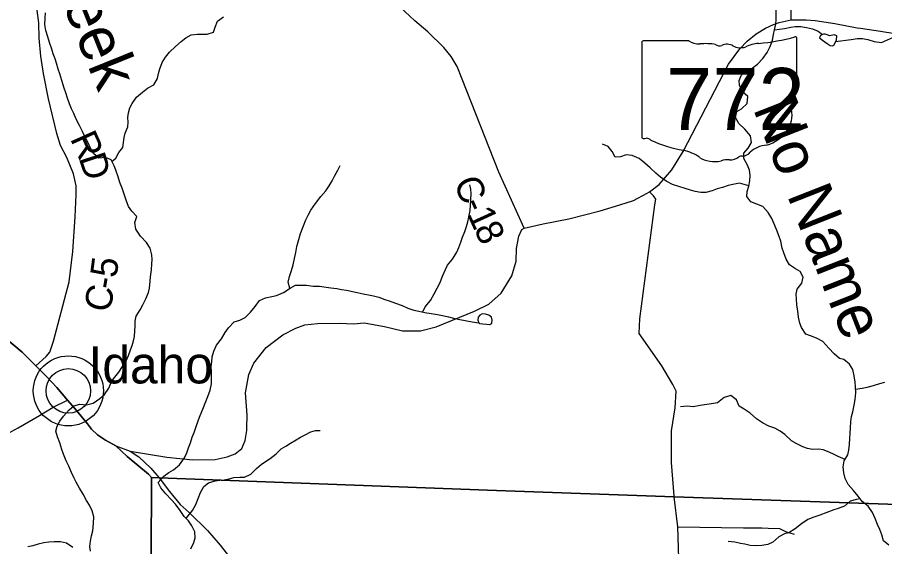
# Model space of a CAD drawing. Extents: x 1578669 to 1989827, y 208020 to 553079.
# Drawn here: x 1785723 to 1795443, y 395188 to 401117 of the extents above; entities that cross this region are included whole.
import ezdxf

# ---------------------------------------------------------------- set-up
doc = ezdxf.new("R2010")
doc.units = 0
for name, color, linetype in [('GM_X_County_Road', 7, 'Continuous'), ('GM_X_County_Road_Text', 7, 'Continuous'), ('GM_X_Minor_Lake', 7, 'Continuous'), ('GM_X_Minor_River', 7, 'Continuous'), ('GM_X_Minor_River_Text', 7, 'Continuous'), ('GM_X_State_Location', 7, 'Continuous'), ('GM_X_State_Route', 7, 'Continuous'), ('GM_X_State_Shield', 7, 'Continuous'), ('GM_X_Township', 7, 'Continuous'), ('GM_X_Township_ROW', 7, 'Continuous'), ('GM_X_Unincorporated', 7, 'Continuous'), ('GM_X_Unincorporated_Location', 7, 'Continuous'), ('GM_X_Unincorporated_Text', 7, 'Continuous')]:
    doc.layers.add(name, color=color, linetype=linetype)

msp = doc.modelspace()

# ---------------------------------------------------------------- linework, layer by layer
at = {"layer": 'GM_X_County_Road'}
for points in [[(1785929.2, 397215.1), (1786046.4, 397318.1), (1786087, 397365.8), (1786128.3, 397491.7), (1786303.3, 398154), (1786342.9, 398494.7), (1786368.9, 398883.7), (1786381.4, 399130.3), (1786382.5, 399230.7), (1786353.8, 399365.4), (1786277.6, 399546.9), (1786206.8, 399680.1), (1786166.2, 399815), (1786072.1, 400205.3), (1786016.9, 400486.9), (1785986.8, 400681.8), (1785968.9, 400884.7), (1785964.7, 401057.3), (1785914.3, 401419.1)], [(1791400.8, 398756), (1791117.4, 399381.9), (1790706, 400424.8), (1790651.4, 400567.9), (1790584.4, 400679), (1790501.4, 400780.2), (1790322.9, 400954.8), (1790178, 401078.8), (1790007.4, 401235.2)], [(1793083.8, 395759.2), (1793054.8, 396130), (1793054.8, 396484.9), (1793093.5, 396741.4), (1793107.5, 396931.1), (1793068.9, 397004.9), (1792945.9, 397212.2), (1792690.3, 397574.3), (1792698.4, 397740.9), (1792867.9, 399015.7), (1792878, 399081.9), (1792851, 399116.1), (1792808.6, 399163.9)], [(1784506.5, 395441.5), (1784631.5, 395570.1), (1784886.6, 395844.1), (1785008.2, 395985.2), (1785137.5, 396100.1), (1785270.7, 396208.9), (1785440.2, 396331.4), (1785567.3, 396428.3), (1785730.4, 396520.7), (1785972, 396658.4), (1786125, 396748.9), (1786286.1, 396828.5)], [(1796261.2, 387201.1), (1795707.2, 387735.4), (1794910.2, 388432.6), (1794803.8, 388549.1), (1794711.5, 388655.5), (1794639.2, 388792.1), (1794623.2, 388966.7), (1794641.5, 389219.6), (1794699.9, 389520.5), (1794722.3, 389934), (1794704.2, 390016.3), (1794648.1, 390174.9), (1794409.3, 390648.8), (1794305.1, 390925.9), (1794262.9, 391056.4), (1794186.7, 391188.9), (1793678.8, 391639), (1793415.8, 391864.1), (1793391.8, 391930.4), (1793156.3, 394466), (1793123.9, 395409.4), (1793084.6, 395748), (1793083.8, 395759.2)]]:
    msp.add_lwpolyline(points, dxfattribs=at)
at = {"layer": 'GM_X_Minor_Lake'}
for points in [[(1794901.3, 400863.1), (1794905.1, 400909.2), (1794875, 400921.1), (1794827, 400908.8), (1794796.9, 400920.7), (1794776.8, 400928.6), (1794756.8, 400928.5), (1794736.8, 400922.4), (1794724.8, 400914.3), (1794710.9, 400888.2), (1794747.1, 400862.3), (1794773.2, 400844.4), (1794797.3, 400824.5), (1794831.5, 400802.6), (1794857.5, 400798.8), (1794871.5, 400804.8)], [(1794871.5, 400804.8), (1794901.3, 400863.1)], [(1790903.8, 397686.3), (1791019.7, 397678), (1791039.7, 397691.9), (1791045.8, 397724), (1791038, 397758.1), (1791008.1, 397782.2), (1790970.1, 397792.4), (1790932.2, 397794.5), (1790904.1, 397780.5), (1790886.1, 397760.6), (1790882, 397724.5)], [(1790882, 397724.5), (1790894.9, 397694.3), (1790903.8, 397686.3)]]:
    msp.add_lwpolyline(points, dxfattribs=at)
at = {"layer": 'GM_X_Minor_River'}
for points in [[(1786123.6, 400706.5), (1786107.8, 400760.7), (1786082.1, 400834.9), (1786064.3, 400899.1), (1786040.5, 400969.4), (1786030.8, 401037.5), (1786035, 401107.7), (1786039.2, 401165.8)], [(1794478.7, 397760.1), (1794468.4, 397824.2), (1794460.1, 397898.3), (1794453.8, 397964.4), (1794451.5, 398014.5), (1794461.3, 398070.7), (1794515, 398141.1), (1794528.8, 398205.3), (1794494.4, 398269.3), (1794444.2, 398299.1), (1794377.9, 398344.9), (1794339.6, 398406.8), (1794311.2, 398478.8), (1794295, 398530.9), (1794278.6, 398608.9), (1794260.3, 398663), (1794232, 398741), (1794199.6, 398813), (1794177.3, 398865), (1794137, 398930.9), (1794078.6, 398996.8), (1794010.4, 399024.5), (1793944.2, 399050.2), (1793899.8, 399112.1), (1793901.6, 399166.2), (1793919.3, 399226.5), (1793931.1, 399286.6), (1793934.8, 399348.8), (1793926.5, 399406.9), (1793906.3, 399462.9), (1793865.9, 399534.8), (1793863.6, 399595), (1793911.4, 399651.3), (1793951.2, 399715.7), (1793940.8, 399789.8), (1793874.4, 399863.6), (1793808, 399929.4), (1793769.7, 399993.4), (1793785.4, 400063.6), (1793839.3, 400093.9), (1793901.2, 400150.4), (1793908.8, 400228.6), (1793848.5, 400284.4), (1793816.1, 400356.4), (1793813.9, 400408.5), (1793833.6, 400464.7), (1793897.5, 400525.2), (1793957.4, 400547.6), (1794019.3, 400592), (1794079.1, 400654.4), (1794124.9, 400724.8), (1794160.6, 400791.1), (1794184.3, 400861.4), (1794198.1, 400923.6), (1794207.8, 400975.8), (1794221.6, 401040), (1794227.3, 401092.1), (1794226.8, 401206.4)], [(1786783.1, 399500.9), (1786827.2, 399539.7), (1786859.3, 399601.7), (1786903.5, 399659.7), (1786911.7, 399715.8), (1786919.9, 399769.9), (1786930, 399820), (1786962.2, 399890), (1786964.4, 399944.1), (1786962.6, 399994.2), (1786968.7, 400046.3), (1786984.9, 400102.4), (1787009.1, 400152.4), (1787059.3, 400224.4), (1787125.4, 400280.3), (1787181.5, 400324.2), (1787253.6, 400362.1), (1787293.8, 400432.1), (1787306, 400488.2), (1787318.1, 400540.3), (1787346.3, 400610.3), (1787382.5, 400672.3), (1787428.7, 400726.3), (1787494.8, 400790.2), (1787557, 400848.1), (1787609.1, 400886.1), (1787669.1, 400919.9), (1787741.1, 400929.7), (1787797.1, 400927.5), (1787849, 400929.4), (1787921, 400951.2), (1787939.2, 401007.2), (1787967.4, 401075.3), (1788031.5, 401123.2)], [(1794208.4, 400978.2), (1794321.9, 400992.4), (1794389.9, 401008.8), (1794440, 401013.1), (1794504.1, 401013.4), (1794568.2, 401001.7), (1794632.4, 400988), (1794698.6, 400960.3), (1794746.6, 400925.4)], [(1794893.2, 400847.2), (1795065.5, 400870), (1795135.5, 400880.4), (1795193.6, 400878.7), (1795255.7, 400867), (1795325.9, 400845.3), (1795406.1, 400835.7), (1795542, 400896.5)], [(1786540.7, 395139.2), (1786536.9, 395191.3), (1786541, 395249.4), (1786555.2, 395309.5), (1786567.4, 395365.6), (1786577.7, 395449.7), (1786579.9, 395521.8), (1786560.2, 395590), (1786530.4, 395652.3), (1786496.6, 395704.5), (1786458.9, 395774.8), (1786419.1, 395845), (1786383.4, 395911.3), (1786355.6, 395961.5), (1786327.8, 396017.7), (1786300, 396088), (1786270.3, 396148.2), (1786238.5, 396222.5), (1786222.7, 396276.6), (1786197, 396352.9), (1786171.2, 396417.1), (1786155.5, 396481.3), (1786169.6, 396539.3), (1786197.8, 396595.4), (1786240, 396651.4), (1786302.1, 396721.3), (1786356.3, 396767.2), (1786422.3, 396783), (1786498.2, 396776.8), (1786574.2, 396796.6), (1786646.3, 396846.5), (1786698.4, 396894.4), (1786746.6, 396964.4), (1786770.8, 397018.4), (1786800.9, 397068.4), (1786861.1, 397144.4), (1786901.3, 397204.4), (1786939.5, 397262.4), (1786969.7, 397328.4), (1786989.9, 397392.5), (1787010, 397442.5), (1787026.2, 397492.6), (1787036.3, 397542.7), (1787040.5, 397604.8), (1787042.7, 397660.9), (1787044.9, 397715), (1787053.1, 397771.1), (1787097.3, 397841.1), (1787127.4, 397897.1), (1787163.6, 397965.2), (1787191.8, 398033.2), (1787204, 398085.3), (1787212.3, 398161.4), (1787216.4, 398211.5), (1787224.7, 398289.7), (1787230.9, 398355.8), (1787233, 398405.9), (1787231.2, 398456), (1787209.5, 398530.2), (1787171.7, 398594.5), (1787104, 398664.9), (1787050.3, 398743.2), (1787040.6, 398817.4), (1787062.8, 398885.5), (1787005, 398947.8), (1786969.2, 398998), (1786943.5, 399070.3), (1786923.7, 399126.5), (1786898, 399204.7), (1786872.2, 399267), (1786852.4, 399329.1), (1786824.7, 399405.4), (1786806.9, 399455.6), (1786773.1, 399519.8), (1786709.3, 399548.1), (1786637.3, 399538.3), (1786575.5, 399592.6), (1786547.7, 399644.8), (1786512, 399717.1), (1786484.2, 399775.3), (1786452.5, 399839.6), (1786418.7, 399905.8), (1786381, 399978.1), (1786355.2, 400038.3), (1786331.4, 400092.5), (1786307.6, 400148.7), (1786283.8, 400210.9), (1786266, 400271.1), (1786248.2, 400323.3), (1786220.5, 400409.6), (1786198.8, 400483.8), (1786181, 400538), (1786163.2, 400602.2), (1786145.4, 400652.3), (1786123.6, 400706.5)], [(1793920.2, 399231.1), (1793815.1, 399258), (1793741, 399245.6), (1793689, 399233.3), (1793625, 399210.9), (1793567, 399194.6), (1793511, 399174.2), (1793437, 399153.8), (1793380.9, 399155.5), (1793320.8, 399167.2), (1793266.7, 399183), (1793208.5, 399198.7), (1793134.3, 399222.4), (1793066.1, 399246.1), (1792995.8, 399283.8), (1792929.6, 399327.6), (1792879.3, 399371.4), (1792812.9, 399431.2), (1792756.6, 399485), (1792690.3, 399534.8), (1792612, 399568.5), (1792545.9, 399576.1), (1792481.9, 399555.8), (1792421.9, 399551.4), (1792389.5, 399613.4), (1792343.2, 399669.3), (1792279, 399695)], [(1788777.9, 398082.2), (1788759, 398152.4), (1788773.2, 398214.5), (1788793.4, 398282.5), (1788813.6, 398346.6), (1788829.9, 398414.7), (1788842.1, 398484.8), (1788856.3, 398548.9), (1788876.5, 398627), (1788894.7, 398697.1), (1788929, 398781.2), (1788957.2, 398847.2), (1788981.4, 398901.3), (1789011.5, 398957.3), (1789063.7, 399033.3), (1789123.9, 399109.2), (1789178.1, 399175.2), (1789218.3, 399231.2), (1789252.4, 399285.2), (1789278.6, 399339.2), (1789314.8, 399405.3), (1789338.9, 399457.3)], [(1790266.6, 397816.8), (1790294.9, 397874.7), (1790351.1, 397944.7), (1790393.3, 398018.7), (1790427.5, 398082.8), (1790459.7, 398148.8), (1790487.9, 398218.8), (1790520.1, 398290.9), (1790544.3, 398342.9), (1790600.5, 398408.9), (1790646.7, 398486.9), (1790670.8, 398539), (1790693, 398597), (1790713.2, 398653.1), (1790737.4, 398717.1), (1790755.6, 398775.2), (1790769.7, 398825.2), (1790783.9, 398879.3), (1790798.1, 398953.4), (1790802.3, 399009.5), (1790806.8, 399141.8), (1790804.9, 399191.9), (1790793.1, 399242.1)], [(1787667.9, 395165.5), (1787700.1, 395235.6), (1787714.3, 395285.6), (1787712.5, 395353.8), (1787678.7, 395420), (1787640.9, 395476.3), (1787593.2, 395526.5), (1787547.4, 395592.8), (1787493.7, 395663.1), (1787449.9, 395713.4), (1787388.2, 395781.8), (1787330.4, 395846.1), (1787302.7, 395908.3), (1787362.8, 395976.2), (1787420.9, 396018.1), (1787471, 396048), (1787539.1, 396105.9), (1787595.3, 396183.9), (1787621.5, 396238), (1787641.7, 396294), (1787661.9, 396352.1), (1787682, 396414.1), (1787704.2, 396466.2), (1787722.4, 396522.2), (1787754.6, 396608.3), (1787772.8, 396658.4), (1787803, 396728.4), (1787835.3, 396812.5), (1787857.4, 396870.5), (1787883.6, 396940.6), (1787899.9, 397012.7), (1787900.1, 397070.8), (1787898.3, 397141), (1787896.5, 397205.1), (1787900.7, 397257.2), (1787906.9, 397315.3), (1787923.1, 397377.4), (1787953.3, 397445.5), (1788009.5, 397517.4), (1788051.7, 397585.5), (1788087.8, 397639.4), (1788152, 397707.4), (1788216, 397725.2), (1788276.1, 397755.1), (1788334.2, 397813), (1788386.4, 397879), (1788436.6, 397945), (1788504.6, 397974.8), (1788574.6, 397988.6), (1788628.6, 398000.5), (1788704.7, 398034.3), (1788780.8, 398084.1), (1788838.8, 398116), (1788900.8, 398117.8), (1788964.7, 398115.6), (1789038.7, 398107.3), (1789108.6, 398105.1), (1789184.5, 398094.8), (1789236.4, 398088.7), (1789304.4, 398078.4), (1789356.3, 398068.2), (1789410.2, 398060), (1789530, 398035.6), (1789597.9, 398021.3), (1789659.8, 398009.1), (1789713.8, 397998.9), (1789773.7, 397982.7), (1789839.5, 397958.4), (1789891.4, 397940.2), (1789961.3, 397915.9), (1790035.2, 397887.6), (1790099, 397861.4), (1790164.9, 397837.1), (1790220.8, 397824.9), (1790290.7, 397812.6), (1790358.6, 397798.4), (1790432.5, 397788.1), (1790504.4, 397773.8), (1790556.3, 397761.6), (1790612.2, 397747.4), (1790682.1, 397731.2), (1790818, 397706.7), (1790895.7, 397693.7)], [(1795487.6, 395203.8), (1795431.3, 395253.6), (1795411, 395319.6), (1795388.7, 395381.7), (1795362.4, 395437.7), (1795336.1, 395503.7), (1795307.7, 395569.7), (1795259.3, 395641.6), (1795189, 395693.3), (1795146.7, 395755.2), (1795094.3, 395819.1), (1795033.9, 395884.9), (1794999.6, 395952.9), (1794983.3, 396016.9), (1794979, 396083.1), (1794990.7, 396149.3), (1795028.4, 396215.6), (1795040.2, 396267.8), (1795047.9, 396334), (1795051.6, 396402.1), (1795055.4, 396456.3), (1795061.1, 396520.4), (1795064.8, 396586.6), (1795070.5, 396646.8), (1795084.3, 396696.9), (1795100, 396773.2), (1795113.7, 396835.4), (1795121.4, 396911.6), (1795115.1, 396979.7), (1795110.9, 397029.8), (1795102.5, 397101.9), (1795084.2, 397172), (1795049.9, 397233.9), (1794985.5, 397285.7), (1794935.4, 397297.5), (1794875.1, 397349.3), (1794818.7, 397413.1), (1794748.3, 397484.9), (1794680.1, 397522.6), (1794609.8, 397550.3), (1794557.7, 397568.1), (1794509.3, 397642), (1794493, 397692), (1794478.7, 397760.1)], [(1795117.6, 396952.4), (1795189.3, 396964), (1795247.3, 396974.4), (1795319.3, 396994.8), (1795389.3, 397015.2), (1795443.3, 397031.5)], [(1794998.4, 396162.8), (1794922.4, 396197), (1794862.2, 396226.8), (1794803.9, 396254.5), (1794753.8, 396274.3), (1794703.7, 396280.1), (1794633.6, 396277.7), (1794579.5, 396289.4), (1794527.3, 396305.2), (1794459.1, 396340.9), (1794396.9, 396374.7), (1794322.4, 396444.5), (1794272.2, 396480.3), (1794210, 396516), (1794143.8, 396537.7), (1794073.5, 396575.5), (1794005.2, 396621.2), (1793934.8, 396683), (1793868.5, 396728.7), (1793812.3, 396762.5), (1793782, 396832.5), (1793719.6, 396882.3), (1793645.6, 396859.8), (1793567.8, 396799.3), (1793501.8, 396787), (1793449.8, 396778.7), (1793375.7, 396768.2), (1793297.7, 396753.8), (1793227.5, 396761.5), (1793155.5, 396755.1)], [(1787607.8, 395511.2), (1787623.1, 395516.4), (1787687.3, 395594.4), (1787723.5, 395660.4), (1787747.7, 395728.5), (1787775.9, 395796.5), (1787812.1, 395862.5), (1787864.2, 395902.5), (1787938.2, 395924.2), (1787990.2, 395932.1), (1788042.2, 395937.9), (1788096.2, 395947.8), (1788150.2, 395961.6), (1788216.1, 395967.4), (1788268.1, 395965.3), (1788338.2, 396001.1), (1788404.3, 396065), (1788454.4, 396107), (1788504.5, 396140.9), (1788556.6, 396174.8), (1788622.7, 396226.7), (1788680.8, 396282.6), (1788730.9, 396314.5), (1788783, 396346.4), (1788847.1, 396386.3), (1788897.1, 396416.2), (1788947.2, 396442.1), (1789013.2, 396475.9), (1789063.2, 396487.8), (1789117.2, 396489.6)], [(1795167.3, 395725), (1795126.8, 395717), (1795054.8, 395696.6), (1794991, 395642.2), (1794923, 395613.8), (1794873, 395599.5), (1794795, 395571), (1794715.1, 395540.5), (1794647.1, 395518.1), (1794581.1, 395491.7), (1794509.2, 395445.3), (1794441.4, 395388.8), (1794369.5, 395344.3), (1794319.5, 395332), (1794255.5, 395299.6), (1794189.7, 395239.2), (1794131.8, 395210.8), (1794067.7, 395200.5), (1794003.6, 395198.1), (1793935.5, 395201.8), (1793877.4, 395215.5), (1793827.3, 395225.3), (1793763.1, 395239), (1793689, 395246.6)], [(1786345, 395179.9), (1786275.2, 395228.2), (1786205.3, 395242.5), (1786135.3, 395242.7), (1786075.4, 395238.9), (1786021.4, 395231.1), (1785957.4, 395217.2), (1785897.4, 395197.4), (1785839.4, 395187.6)]]:
    msp.add_lwpolyline(points, dxfattribs=at)
at = {"layer": 'GM_X_State_Route'}
for points in [[(1794394.3, 401090.8), (1794393, 401338.2), (1794402.1, 401411.1), (1794413.8, 401480.1), (1794438.6, 401559.6), (1794474.9, 401713.7), (1794563, 401939.9), (1794657.6, 402234.5), (1794844.7, 402797.1), (1794904.2, 402969.3), (1794966.7, 403266), (1795167.4, 404037.4), (1795221.1, 404231.7), (1795238.2, 404362.1), (1795259.7, 404546.7), (1795248.7, 404681.2), (1795233.7, 404815.9), (1795217.7, 404874.2), (1795194.9, 404980.8), (1795171.2, 405068.5), (1795138.3, 405190), (1795039.1, 405542)], [(1792473, 399017.8), (1792474.1, 399018.2), (1792629.6, 399065.1), (1792782.8, 399146.3), (1792808.6, 399163.9), (1792914, 399243.8), (1793057.8, 399407.3), (1793185.9, 399613.2), (1793691.4, 400593.2), (1793821.4, 400762.7), (1793900.8, 400848.6), (1794001.1, 400933.3), (1794107.9, 400994.4), (1794195.1, 401036.1), (1794261.5, 401058.3), (1794394.3, 401090.8)], [(1794394.3, 401090.8), (1794562.3, 401090.8), (1794665.1, 401083), (1794885.2, 401046.5), (1795135.2, 400999.7), (1795171.2, 400994.4)], [(1795171.2, 400994.4), (1795395.6, 400961.9), (1795695.1, 400913.7)], [(1788294.6, 396490.5), (1788295.3, 396524.6), (1788298.4, 396662.1), (1788280, 396909.4), (1788316.7, 397115.4), (1788371.8, 397244.7), (1788512, 397418.3), (1788697.7, 397560.7), (1788843.7, 397635.8), (1788942.8, 397673.8), (1789087.4, 397686.7), (1789332.1, 397691.3), (1789490.3, 397683.8), (1789608.8, 397695.3), (1789836.3, 397654.1), (1790039.7, 397607.5), (1790242.1, 397605), (1790415.5, 397649.4), (1790844.4, 397824.6), (1791006.6, 397903.4), (1791145.7, 398028.8), (1791264.4, 398222.9), (1791314.2, 398384.5), (1791315.4, 398527), (1791342.6, 398666.9), (1791375.6, 398739.7), (1791400.8, 398756), (1791615.9, 398803.5), (1791901.4, 398859.7), (1792253.4, 398951.5), (1792473, 399017.8)], [(1785493.6, 397595.2), (1785494.7, 397594.5), (1785591.2, 397524.5), (1785778.6, 397367.7), (1785929.2, 397215.1), (1786051.7, 397091.3), (1786165.6, 396972.7), (1786248.6, 396873.4)], [(1786248.6, 396873.4), (1786286.1, 396828.5), (1786367.7, 396737.4), (1786464.9, 396616.6)], [(1786464.9, 396616.6), (1786508.7, 396562.3), (1786553.1, 396505.7), (1786622.3, 396439.8), (1786710.3, 396380.8), (1786827.9, 396319.3), (1786988.3, 396259.4)], [(1786988.3, 396259.4), (1787397.7, 396190.1), (1787689.7, 396161.6), (1787940.4, 396166.1), (1788075.3, 396193.3), (1788164.3, 396229.4), (1788239.8, 396286), (1788275.9, 396377.5), (1788294.5, 396487.6), (1788294.6, 396490.5)], [(1786988.3, 396259.4), (1787084.7, 396195.2), (1787218.5, 396067.8), (1787310.4, 395958), (1787426.7, 395807), (1787548.4, 395661), (1787648.4, 395571.7), (1787855.2, 395369), (1787995.8, 395205.4), (1788155.3, 395001.3)]]:
    msp.add_lwpolyline(points, dxfattribs=at)
at = {"layer": 'GM_X_State_Shield'}
for p, q in [((1793246.2, 400853.8), (1792736.6, 400853.8)), ((1794459.7, 400327.3), (1794459.7, 400880)), ((1792719.5, 400835.7), (1792719.5, 399779)), ((1794459.5, 400327.4), (1794459.7, 400327.3))]:
    msp.add_line(p, q, dxfattribs=at)
for centre, major_axis, start_param, end_param in [((1792739.4, 400837.9), (20.2, 0), 1.712693, 3.28349), ((1793367.6, 400976.5), (195.5, 0), 4.042523, 4.731795), ((1793839.8, 402294.4), (1845.5, 0), 4.814394, 5.042369), ((1794440.3, 400882.3), (19.4, 0), 6.141152, 7.989035), ((1793432.4, 400260.6), (702, 0), 1.404758, 1.657858), ((1793591.8, 400843.4), (56.4, 0), 3.836095, 5.185415), ((1793674.6, 400721.3), (117.3, 0), 0.950623, 2.079405), ((1793826, 400888.8), (141.1, 0), 4.081561, 5.145723), ((1794075.2, 400531.1), (371.3, 0), 1.699011, 2.107814), ((1794455.2, 400286.7), (30, 0), 1.883978, 3.671073), ((1794264.4, 400216.8), (180, 0), 5.934695, 6.695948), ((1794439, 400325.2), (20.7, 0), 5.05454, 6.418171), ((1794529.1, 400096), (130.9, 0), 2.387724, 3.262537), ((1793943.1, 400025.7), (461.6, 0), 5.101752, 6.440018), ((1792739.6, 399776.7), (20.3, 0), 3.00124, 4.508301), ((1792742.7, 399884.8), (155.2, 0), 4.665946, 4.897461), ((1792774.4, 399718.1), (56, 0), 0.519207, 1.627899), ((1793481, 400667.4), (1332.7, 0), 4.195997, 4.488961), ((1794137.8, 399482.4), (252.8, 0), 1.647645, 2.488434), ((1793083.7, 399304.3), (417, 0), 0.823519, 1.323587), ((1793817.5, 399676.6), (149.1, 0), 4.937069, 5.64225), ((1793534.7, 399712.8), (264.6, 0), 4.026481, 4.996735), ((1793687.5, 399347.5), (217.4, 0), 1.495662, 1.94098), ((1793706.9, 399633.7), (141, 0), 4.691044, 5.507374), ((1793834.4, 399531.4), (39.7, 0), 1.147584, 2.315152)]:
    msp.add_ellipse(centre, major_axis=major_axis, ratio=0.8, start_param=start_param, end_param=end_param, dxfattribs=at)
at = {"layer": 'GM_X_Township'}
for points in [[(1804835, 395343.7), (1793084.6, 395748), (1791093.9, 395819), (1787310.4, 395958), (1787226.7, 395961.1), (1787194, 396000.8), (1786953.3, 396199.1), (1786827.9, 396319.3), (1786710.3, 396380.8), (1786622.3, 396439.8), (1786553.1, 396505.7), (1786508.7, 396562.3), (1786367.6, 396737.4), (1786286.1, 396828.5), (1786165.6, 396972.7), (1786051.7, 397091.3), (1785929.2, 397215), (1785778.6, 397367.7), (1785591.2, 397524.5)], [(1785591.2, 397524.5), (1785778.6, 397367.7), (1785929.2, 397215), (1786051.7, 397091.3), (1786165.6, 396972.7), (1786286.1, 396828.5), (1786367.6, 396737.4), (1786508.7, 396562.3), (1786553.1, 396505.7), (1786622.3, 396439.8), (1786710.3, 396380.8), (1786827.9, 396319.3), (1786953.3, 396199.1), (1787194, 396000.8), (1787226.7, 395961.1), (1787192.7, 387857.3)], [(1813574.5, 362259.2), (1795322, 364551.2), (1793208.8, 364816.4), (1791051.2, 365124.4), (1790671.6, 365178.6), (1790139.8, 365258.8), (1788627.9, 365489.7), (1786428.7, 365785.4), (1786212.4, 365817.6), (1786220.7, 365918.9), (1786433.8, 371260.6), (1786521, 373852.3), (1786899.4, 381582.4), (1786904.4, 381775.1), (1786921.8, 382107.3), (1787173.2, 387356.9), (1787185.7, 387525.7), (1787192.7, 387857.3), (1787226.7, 395961.1), (1787310.4, 395958), (1791093.9, 395819), (1793084.6, 395748), (1804835, 395343.7)]]:
    msp.add_lwpolyline(points, dxfattribs=at)
at = {"layer": 'GM_X_Township_ROW'}
msp.add_lwpolyline([(1793123.9, 395409.4), (1793861.2, 395400.9), (1794066.8, 395400.9), (1794138.8, 395393.9), (1794264.2, 395391.1), (1794332.6, 395357.9), (1794430.1, 395326.8)], dxfattribs=at)
at = {"layer": 'GM_X_Unincorporated'}
for radius in [392.8, 249]:
    msp.add_circle((1786294.2, 396932.9), radius, dxfattribs=at)
at = {"layer": 'GM_X_Unincorporated_Location'}
msp.add_line((1786294.2, 396932.9), (1786294.2, 396932.9), dxfattribs=at)

# ---------------------------------------------------------------- texts
at = {"layer": 'GM_X_County_Road_Text'}
for s, rotation, p in [('R', 294.10674, (1786310.3, 399759.6)), ('D', 288.35087, (1786408, 399542.1)), ('C', 292.80091, (1790608.2, 399266.3)), ('-', 294.38233, (1790707.4, 399030.9)), ('1', 294.53134, (1790758.6, 398917.9)), ('8', 294.59531, (1790835.4, 398749.5)), ('5', 82.57173, (1786833.8, 398190.9)), ('-', 80.71232, (1786812.4, 398058.8)), ('C', 77.10923, (1786753.4, 397798.4))]:
    msp.add_text(s, height=300, rotation=rotation, dxfattribs=at).set_placement(p)
at = {"layer": 'GM_X_Minor_River_Text'}
for s, height, rotation, p in [('Creek', 500.05, 291.95641, (1785964.4, 401924.7)), ('No Name', 500.04, 291.43657, (1793963.2, 400098.8))]:
    msp.add_text(s, height=height, rotation=rotation, dxfattribs=at).set_placement(p)
at = {"layer": 'GM_X_State_Location'}
for s in ['s', 'r']:
    msp.add_text(s, height=1, dxfattribs=at).set_placement((1793570, 400237.1))
msp.add_text('772', height=1, rotation=0.00001, dxfattribs=at).set_placement((1793217, 400164.3))
at = {"layer": 'GM_X_State_Shield'}
msp.add_text('772', height=696.1, dxfattribs=at).set_placement((1792993.6, 399853.5))
at = {"layer": 'GM_X_Unincorporated_Text'}
msp.add_text('Idaho', height=417, rotation=0.00001, dxfattribs=at).set_placement((1786520.2, 397016.6))

doc.saveas('drawing.dxf')
